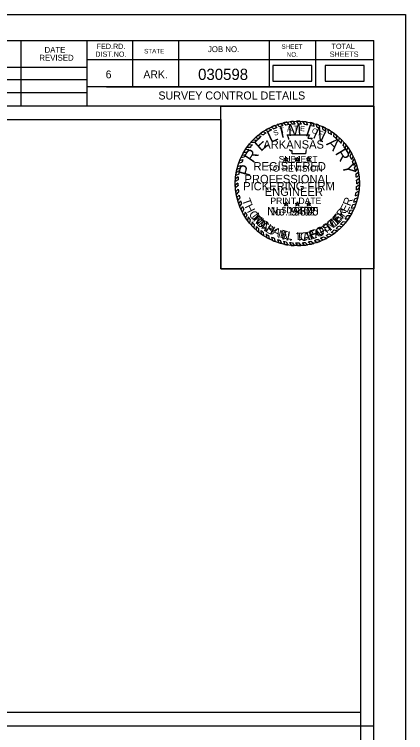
# Model space of a CAD drawing. Extents: x 818639 to 819473, y 1805980 to 1806194.
# Drawn here: x 818913.8 to 818972.5, y 1806086 to 1806193.7 of the extents above; entities that cross this region are included whole.
import ezdxf

# ---------------------------------------------------------------- set-up
doc = ezdxf.new("R2010")
doc.units = 0
for name, color, linetype in [('R_Border', 7, 'Continuous'), ('R_Border Notes', 7, 'Continuous'), ('R_Border Plan-Plan', 7, 'Continuous'), ('R_Border Title', 7, 'Continuous'), ('R_No Plot', 7, 'Continuous'), ('STAMP_PE_CRAFTON', 7, 'Continuous'), ('STAMP_PE_FOSTER', 7, 'Continuous'), ('STAMP_PE_SEAL-INFO', 7, 'Continuous'), ('STAMP_PE_TAEGTMEYER', 7, 'Continuous'), ('STAMP_PE_TXT', 7, 'Continuous'), ('STAMP_PRELIMINARY', 7, 'Continuous')]:
    doc.layers.add(name, color=color, linetype=linetype)

msp = doc.modelspace()

# ---------------------------------------------------------------- linework, layer by layer
at = {"layer": 'R_Border'}
for p, q in [((818651.6, 1806189.77), (818967.78, 1806189.77)), ((818914.82, 1806179.89), (818914.82, 1806189.77)), ((818924.68, 1806189.77), (818924.68, 1806179.89)), ((818931.52, 1806189.77), (818931.52, 1806182.83)), ((818938.46, 1806189.77), (818938.46, 1806182.83)), ((818952.04, 1806189.77), (818952.04, 1806182.83)), ((818958.98, 1806189.77), (818958.98, 1806182.83)), ((818967.78, 1805984.31), (818967.78, 1806189.77)), ((818967.78, 1806186.83), (818924.68, 1806186.83)), ((818967.78, 1806186.85), (818967.78, 1806186.85)), ((818905.14, 1806185.75), (818924.68, 1806185.75)), ((818905.14, 1806183.89), (818924.68, 1806183.89)), ((818905.14, 1806181.95), (818924.68, 1806181.95)), ((818967.78, 1806182.83), (818924.68, 1806182.83)), ((818927.64, 1806182.83), (818967.78, 1806182.83)), ((818967.78, 1806179.89), (818905.14, 1806179.89))]:
    msp.add_line(p, q, dxfattribs=at)
at = {"layer": 'R_Border Plan-Plan'}
msp.add_line((818651.6, 1806087.04), (818967.78, 1806087.04), dxfattribs=at)
at = {"layer": 'R_Border Title'}
for points in [[(818952.59, 1806183.68), (818958.43, 1806183.68), (818958.43, 1806185.99), (818952.59, 1806185.99)], [(818960.46, 1806183.68), (818966.3, 1806183.68), (818966.3, 1806185.99), (818960.46, 1806185.99)]]:
    msp.add_lwpolyline(points, close=True, dxfattribs=at)
at = {"layer": 'R_No Plot'}
for points in [[(818639.19, 1806193.67), (818972.53, 1806193.67), (818972.53, 1805980.33), (818639.19, 1805980.33)], [(818965.78, 1806089.04), (818653.6, 1806089.04), (818653.6, 1806187.77), (818903.14, 1806187.77), (818903.14, 1806177.89), (818920.68, 1806177.89), (818944.78, 1806177.89), (818944.78, 1806155.56), (818965.78, 1806155.56)], [(818653.6, 1806187.77), (818903.14, 1806187.77), (818903.14, 1806177.89), (818920.68, 1806177.89), (818944.78, 1806177.89), (818944.78, 1806155.56), (818965.78, 1806155.56), (818965.78, 1805986.31), (818653.6, 1805986.31)], [(818944.78, 1806179.89), (818967.78, 1806179.89), (818967.78, 1806155.56), (818944.78, 1806155.56)]]:
    msp.add_lwpolyline(points, close=True, dxfattribs=at)
at = {"layer": 'STAMP_PE_SEAL-INFO'}
for p, q in [((818954.7, 1806177.52), (818955, 1806177.16)), ((818955.22, 1806177.6), (818955.5, 1806177.21)), ((818955.95, 1806177.24), (818955.64, 1806177.64)), ((818956.45, 1806177.25), (818956.17, 1806177.66)), ((818956.91, 1806177.23), (818956.65, 1806177.65)), ((818957.41, 1806177.18), (818957.12, 1806177.62)), ((818957.84, 1806177.11), (818957.58, 1806177.57)), ((818951.95, 1806176.59), (818952.42, 1806176.37)), ((818952.38, 1806176.8), (818952.77, 1806176.53)), ((818952.89, 1806177.02), (818953.19, 1806176.69)), ((818953.24, 1806177.15), (818953.62, 1806176.84)), ((818953.83, 1806177.33), (818954.12, 1806176.98)), ((818954.22, 1806177.43), (818954.58, 1806177.08)), ((818958.4, 1806176.99), (818958.23, 1806177.45)), ((818958.8, 1806176.88), (818958.64, 1806177.35)), ((818959.26, 1806176.74), (818959.11, 1806177.22)), ((818959.67, 1806176.58), (818959.53, 1806177.07)), ((818960.14, 1806176.37), (818960.03, 1806176.87)), ((818960.58, 1806176.14), (818960.49, 1806176.65)), ((818960.97, 1806175.92), (818960.93, 1806176.42)), ((818950.32, 1806175.5), (818950.85, 1806175.4)), ((818950.7, 1806175.83), (818951.15, 1806175.63)), ((818951.12, 1806176.1), (818951.56, 1806175.9)), ((818951.51, 1806176.34), (818951.94, 1806176.12)), ((818954.75, 1806175.63), (818958.1, 1806175.63)), ((818954.88, 1806175.32), (818954.75, 1806175.63)), ((818958.1, 1806175.63), (818957.87, 1806175.13)), ((818961.4, 1806175.63), (818961.37, 1806176.14)), ((818961.76, 1806175.36), (818961.8, 1806175.85)), ((818962.21, 1806174.99), (818962.23, 1806175.51)), ((818949.32, 1806174.54), (818949.84, 1806174.5)), ((818949.64, 1806174.88), (818950.19, 1806174.84)), ((818949.98, 1806175.2), (818950.44, 1806175.07)), ((818954.98, 1806175.02), (818954.88, 1806175.32)), ((818954.99, 1806174.91), (818954.98, 1806175.02)), ((818957.87, 1806175.13), (818958.51, 1806175.13)), ((818958.51, 1806175.13), (818958.36, 1806174.91)), ((818962.52, 1806174.7), (818962.59, 1806175.2)), ((818962.88, 1806174.32), (818962.95, 1806174.85)), ((818963.16, 1806174.01), (818963.29, 1806174.48)), ((818948.46, 1806173.41), (818948.98, 1806173.45)), ((818948.7, 1806173.76), (818949.2, 1806173.75)), ((818948.97, 1806174.13), (818949.52, 1806174.15)), ((818955.18, 1806173.2), (818955.15, 1806173.42)), ((818955.49, 1806173.2), (818955.18, 1806173.2)), ((818955.49, 1806172.77), (818955.49, 1806173.2)), ((818957.62, 1806173.42), (818957.54, 1806173.11)), ((818963.48, 1806173.59), (818963.61, 1806174.09)), ((818963.7, 1806173.28), (818963.88, 1806173.74)), ((818964.01, 1806172.78), (818964.19, 1806173.27)), ((818947.8, 1806172.2), (818948.3, 1806172.3)), ((818947.98, 1806172.59), (818948.48, 1806172.65)), ((818948.22, 1806173.01), (818948.7, 1806173.03)), ((818957.52, 1806172.77), (818955.49, 1806172.77)), ((818957.54, 1806173.11), (818957.52, 1806172.77)), ((818964.21, 1806172.41), (818964.43, 1806172.86)), ((818964.44, 1806171.93), (818964.66, 1806172.41)), ((818947.31, 1806170.86), (818947.78, 1806171.03)), ((818947.46, 1806171.36), (818947.95, 1806171.5)), ((818947.61, 1806171.77), (818948.12, 1806171.91)), ((818964.58, 1806171.59), (818964.84, 1806172.02)), ((818964.77, 1806171.04), (818965.04, 1806171.52)), ((818964.88, 1806170.68), (818965.17, 1806171.13)), ((818947.57, 1806170.2), (818947.1, 1806169.95)), ((818947.2, 1806170.45), (818947.67, 1806170.64)), ((818965.01, 1806170.12), (818965.33, 1806170.57)), ((818965.08, 1806169.74), (818965.44, 1806170.09)), ((818947.38, 1806168.88), (818946.96, 1806168.63)), ((818947.42, 1806169.31), (818946.98, 1806169.03)), ((818947.48, 1806169.74), (818947.03, 1806169.52)), ((818965.15, 1806169.23), (818965.52, 1806169.57)), ((818965.18, 1806168.81), (818965.57, 1806169.1)), ((818947.37, 1806168.39), (818946.96, 1806168.05)), ((818947.37, 1806167.98), (818946.98, 1806167.66)), ((818965.18, 1806167.89), (818965.6, 1806168.17)), ((818965.19, 1806168.29), (818965.6, 1806168.62)), ((818947.41, 1806167.49), (818947.04, 1806167.13)), ((818947.46, 1806167.06), (818947.11, 1806166.69)), ((818965.09, 1806166.99), (818965.54, 1806167.21)), ((818965.14, 1806167.38), (818965.58, 1806167.64)), ((818947.54, 1806166.6), (818947.2, 1806166.23)), ((818947.63, 1806166.18), (818947.32, 1806165.77)), ((818947.76, 1806165.73), (818947.46, 1806165.32)), ((818964.75, 1806165.55), (818965.24, 1806165.75)), ((818964.89, 1806166.04), (818965.37, 1806166.24)), ((818965, 1806166.49), (818965.46, 1806166.69)), ((818947.9, 1806165.31), (818947.61, 1806164.9)), ((818948.06, 1806164.88), (818947.8, 1806164.46)), ((818964.4, 1806164.65), (818964.89, 1806164.75)), ((818964.61, 1806165.17), (818965.1, 1806165.3)), ((818948.23, 1806164.5), (818948.01, 1806164.04)), ((818948.47, 1806164.04), (818948.28, 1806163.55)), ((818948.7, 1806163.64), (818948.52, 1806163.17)), ((818963.79, 1806163.54), (818964.27, 1806163.53)), ((818963.97, 1806163.82), (818964.47, 1806163.87)), ((818964.24, 1806164.32), (818964.73, 1806164.39)), ((818948.91, 1806163.33), (818948.8, 1806162.78)), ((818949.19, 1806162.94), (818949.09, 1806162.41)), ((818949.49, 1806162.56), (818949.41, 1806162.04)), ((818963.15, 1806162.65), (818963.61, 1806162.57)), ((818963.45, 1806163.04), (818963.96, 1806163.05)), ((818949.79, 1806162.22), (818949.73, 1806161.7)), ((818950.12, 1806161.9), (818950.09, 1806161.37)), ((818950.46, 1806161.58), (818950.46, 1806161.05)), ((818961.83, 1806161.36), (818962.3, 1806161.22)), ((818962.1, 1806161.58), (818962.57, 1806161.46)), ((818962.51, 1806161.96), (818962.95, 1806161.82)), ((818962.76, 1806162.22), (818963.24, 1806162.13)), ((818950.82, 1806161.29), (818950.84, 1806160.76)), ((818951.16, 1806161.04), (818951.2, 1806160.52)), ((818951.59, 1806160.76), (818951.65, 1806160.25)), ((818951.94, 1806160.55), (818952.03, 1806160.04)), ((818952.42, 1806160.3), (818952.57, 1806159.78)), ((818960.2, 1806160.33), (818960.69, 1806160.12)), ((818960.61, 1806160.54), (818961.03, 1806160.31)), ((818961.03, 1806160.79), (818961.48, 1806160.59)), ((818961.37, 1806161.02), (818961.81, 1806160.83)), ((818952.79, 1806160.13), (818952.96, 1806159.62)), ((818953.28, 1806159.94), (818953.49, 1806159.44)), ((818953.69, 1806159.81), (818953.92, 1806159.32)), ((818954.2, 1806159.67), (818954.41, 1806159.2)), ((818954.6, 1806159.58), (818954.85, 1806159.12)), ((818955.1, 1806159.5), (818955.34, 1806159.06)), ((818955.54, 1806159.45), (818955.81, 1806159.02)), ((818956.02, 1806159.43), (818956.32, 1806159.01)), ((818956.48, 1806159.42), (818956.82, 1806159.03)), ((818957, 1806159.45), (818957.32, 1806159.07)), ((818957.44, 1806159.5), (818957.81, 1806159.14)), ((818957.88, 1806159.57), (818958.27, 1806159.23)), ((818958.37, 1806159.67), (818958.75, 1806159.35)), ((818958.83, 1806159.79), (818959.25, 1806159.5)), ((818959.33, 1806159.96), (818959.77, 1806159.69)), ((818959.75, 1806160.12), (818960.17, 1806159.86))]:
    msp.add_line(p, q, dxfattribs=at)
for radius, start, end in [(9.32, 99.7525, 102.7765), (9.32, 93.9381, 96.5517), (9.32, 87.7298, 90.6707), (9.32, 81.9732, 84.8236), (9.32, 117.6544, 120.8099), (9.32, 111.3124, 114.7026), (8.91, 110.3086, 113.1659), (9.32, 105.2339, 109.0352), (8.91, 104.0352, 107.3615), (8.91, 98.258, 101.0329), (8.91, 92.1102, 95.0367), (8.91, 85.9628, 88.9097), (8.91, 79.9264, 82.696), (9.32, 75.3125, 77.9426), (8.91, 73.5575, 76.2314), (9.32, 69.6061, 72.3058), (8.91, 67.6248, 70.504), (9.32, 63.1329, 66.2704), (9.32, 56.9003, 60.0942), (9.32, 129.7326, 132.5376), (8.91, 127.5297, 130.9683), (9.32, 123.6199, 126.5906), (8.91, 121.9746, 125.11), (8.91, 115.6869, 119.1583), (8.91, 61.1558, 64.3784), (8.91, 54.9238, 58.2702), (8.91, 48.3016, 52.0395), (9.32, 50.3492, 53.7159), (9.32, 135.4021, 138.3031), (8.91, 133.1331, 136.2562), (8.91, 42.2212, 45.5512), (9.32, 44.3405, 47.3929), (9.32, 38.1247, 41.2316), (9.32, 147.0072, 149.899), (9.32, 141.6056, 144.4486), (8.91, 145.0197, 148.2104), (8.91, 139.301, 142.5873), (8.91, 36.135, 39.5311), (8.91, 29.9032, 33.6645), (9.32, 31.9614, 35.4294), (9.32, 152.864, 155.5189), (8.91, 151.0315, 153.573), (8.91, 23.7732, 27.2211), (9.32, 25.9391, 29.0125), (9.32, 158.4077, 161.0701), (8.91, 162.4331, 165.0013), (8.91, 156.3402, 159.2319), (8.91, 17.6802, 21.4251), (9.32, 19.9538, 23.3141), (9.32, 13.8421, 17.4447), (9.32, 170.0003, 172.6878), (9.32, 164.3068, 166.894), (8.91, 167.9048, 170.9039), (8.91, 11.5444, 15.2364), (9.32, 7.5852, 10.8621), (9.32, 175.7409, 178.2066), (8.91, 173.73, 176.4734), (8.91, 5.7599, 9.0606), (9.32, 1.7215, 4.7268), (9.32, 181.7251, 184.1626), (8.91, 179.6454, 182.2633), (8.91, 353.8632, 357.1274), (8.91, 359.7329, 3.0639), (9.32, 355.7156, 358.9569), (9.32, 187.4204, 190.1927), (8.91, 185.4539, 188.234), (8.91, 348.0778, 351.3435), (9.32, 349.8305, 353.0885), (9.32, 193.0369, 195.9973), (8.91, 191.2274, 193.9858), (8.91, 196.9675, 199.8353), (8.91, 341.777, 345.0925), (9.32, 343.8925, 347.035), (9.32, 198.8967, 201.6281), (8.91, 202.7761, 205.4791), (8.91, 335.6038, 339.1858), (9.32, 337.3837, 340.9933), (9.32, 204.5479, 207.4328), (9.32, 210.8636, 213.6571), (8.91, 208.7883, 211.7934), (8.91, 323.5851, 327.4407), (9.32, 325.4405, 328.9872), (8.91, 329.5549, 333.2076), (9.32, 331.4037, 334.9332), (9.32, 216.6115, 219.491), (8.91, 214.1838, 217.2747), (8.91, 220.3909, 223.3056), (8.91, 316.6531, 320.3711), (9.32, 318.2846, 321.8043), (9.32, 222.48, 225.3801), (9.32, 228.3665, 231.348), (8.91, 226.2494, 229.2407), (8.91, 304.823, 308.5143), (8.91, 310.7744, 314.3161), (9.32, 312.4518, 315.6633), (8.91, 232.229, 234.9336), (9.32, 234.295, 236.9452), (8.91, 238.2223, 240.8353), (8.91, 244.3204, 246.9486), (8.91, 292.8745, 296.1185), (8.91, 299.0768, 302.1724), (9.32, 300.621, 303.8703), (9.32, 306.3721, 310.208), (9.32, 240.1977, 242.8613), (9.32, 246.576, 249.1558), (8.91, 250.3491, 253.1216), (9.32, 252.5967, 255.3252), (8.91, 256.505, 259.1192), (9.32, 258.4433, 261.1398), (8.91, 262.3783, 265.2012), (8.91, 268.3215, 271.277), (8.91, 274.6157, 277.4486), (8.91, 280.3459, 283.5814), (9.32, 282.3199, 285.3702), (8.91, 286.6423, 289.9783), (9.32, 288.5709, 291.9733), (9.32, 294.6481, 298.2166), (9.32, 264.1978, 267.1009), (9.32, 270.2548, 273.3361), (9.32, 276.4239, 279.4357)]:
    msp.add_arc((818956.28, 1806168.33), radius, start, end, dxfattribs=at)
at = {"layer": 'STAMP_PE_TXT'}
for p, q in [((818954.51, 1806172.05), (818954.58, 1806172.28)), ((818954.58, 1806172.28), (818954.66, 1806172.05)), ((818956.21, 1806172.05), (818956.28, 1806172.28)), ((818956.28, 1806172.28), (818956.36, 1806172.05)), ((818957.9, 1806172.05), (818957.98, 1806172.28)), ((818957.98, 1806172.28), (818958.05, 1806172.05)), ((818954.46, 1806171.91), (818954.26, 1806172.05)), ((818954.26, 1806172.05), (818954.51, 1806172.05)), ((818954.38, 1806171.67), (818954.46, 1806171.91)), ((818954.58, 1806171.82), (818954.38, 1806171.67)), ((818954.78, 1806171.67), (818954.58, 1806171.82)), ((818954.66, 1806172.05), (818954.9, 1806172.05)), ((818954.9, 1806172.05), (818954.71, 1806171.91)), ((818954.71, 1806171.91), (818954.78, 1806171.67)), ((818956.16, 1806171.91), (818955.96, 1806172.05)), ((818955.96, 1806172.05), (818956.21, 1806172.05)), ((818956.08, 1806171.67), (818956.16, 1806171.91)), ((818956.28, 1806171.82), (818956.08, 1806171.67)), ((818956.48, 1806171.67), (818956.28, 1806171.82)), ((818956.36, 1806172.05), (818956.6, 1806172.05)), ((818956.6, 1806172.05), (818956.4, 1806171.91)), ((818956.4, 1806171.91), (818956.48, 1806171.67)), ((818957.86, 1806171.91), (818957.66, 1806172.05)), ((818957.66, 1806172.05), (818957.9, 1806172.05)), ((818957.78, 1806171.67), (818957.86, 1806171.91)), ((818957.98, 1806171.82), (818957.78, 1806171.67)), ((818958.18, 1806171.67), (818957.98, 1806171.82)), ((818958.05, 1806172.05), (818958.3, 1806172.05)), ((818958.3, 1806172.05), (818958.1, 1806171.91)), ((818958.1, 1806171.91), (818958.18, 1806171.67)), ((818954.46, 1806165.2), (818954.26, 1806165.34)), ((818954.26, 1806165.34), (818954.51, 1806165.34)), ((818954.38, 1806164.97), (818954.46, 1806165.2)), ((818954.58, 1806165.11), (818954.38, 1806164.97)), ((818954.51, 1806165.34), (818954.58, 1806165.58)), ((818954.58, 1806165.58), (818954.66, 1806165.34)), ((818954.78, 1806164.97), (818954.58, 1806165.11)), ((818954.66, 1806165.34), (818954.9, 1806165.34)), ((818954.9, 1806165.34), (818954.71, 1806165.2)), ((818954.71, 1806165.2), (818954.78, 1806164.97)), ((818956.16, 1806165.2), (818955.96, 1806165.34)), ((818955.96, 1806165.34), (818956.21, 1806165.34)), ((818956.08, 1806164.97), (818956.16, 1806165.2)), ((818956.28, 1806165.11), (818956.08, 1806164.97)), ((818956.21, 1806165.34), (818956.28, 1806165.58)), ((818956.28, 1806165.58), (818956.36, 1806165.34)), ((818956.48, 1806164.97), (818956.28, 1806165.11)), ((818956.36, 1806165.34), (818956.6, 1806165.34)), ((818956.6, 1806165.34), (818956.4, 1806165.2)), ((818956.4, 1806165.2), (818956.48, 1806164.97)), ((818957.86, 1806165.2), (818957.66, 1806165.34)), ((818957.66, 1806165.34), (818957.9, 1806165.34)), ((818957.78, 1806164.97), (818957.86, 1806165.2)), ((818957.98, 1806165.11), (818957.78, 1806164.97)), ((818957.9, 1806165.34), (818957.98, 1806165.58)), ((818957.98, 1806165.58), (818958.05, 1806165.34)), ((818958.18, 1806164.97), (818957.98, 1806165.11)), ((818958.05, 1806165.34), (818958.3, 1806165.34)), ((818958.3, 1806165.34), (818958.1, 1806165.2)), ((818958.1, 1806165.2), (818958.18, 1806164.97))]:
    msp.add_line(p, q, dxfattribs=at)
at = {"layer": 'STAMP_PRELIMINARY'}
msp.add_circle((818956.28, 1806168.33), 9.32, dxfattribs=at)

# ---------------------------------------------------------------- texts
at = {"layer": 'R_Border'}
for s, height, p in [('DATE', 0.879, (818918.34, 1806187.91)), ('FED.RD.', 0.782, (818926.16, 1806188.49)), ('STATE', 0.684, (818933.28, 1806187.81)), ('JOB NO.', 0.879, (818942.86, 1806188.01)), ('SHEET', 0.684, (818953.9, 1806188.49)), ('TOTAL', 0.782, (818961.42, 1806188.49)), ('REVISED', 0.879, (818917.56, 1806186.73)), ('DIST.NO.', 0.782, (818925.96, 1806187.31)), ('NO.', 0.684, (818954.68, 1806187.31)), ('SHEETS', 0.782, (818961.14, 1806187.31)), ('6', 1.17, (818927.52, 1806184.09)), ('ARK.', 1.172, (818933.18, 1806184.09))]:
    msp.add_text(s, height=height, dxfattribs=at).set_placement(p)
at = {"layer": 'R_Border Notes'}
for s, height, p in [('030598', 1.68, (818941.39, 1806183.84)), ('SURVEY CONTROL DETAILS', 1.2, (818935.43, 1806180.91))]:
    msp.add_text(s, height=height, dxfattribs=at).set_placement(p)
at = {"layer": 'STAMP_PE_CRAFTON'}
msp.add_text('No. 12370', height=1.25, dxfattribs=at).set_placement((818951.74, 1806163.53))
for s, rotation, p in [('T', 310.7442, (818949.25, 1806163.23)), ('N', 49.2411, (818962.56, 1806162.36)), ('O', 317.6422, (818949.91, 1806162.42)), ('N', 324.4537, (818950.76, 1806161.64)), ('T', 34.1136, (818960.86, 1806160.97)), ('O', 41.8391, (818961.72, 1806161.58)), ('Y', 331.1686, (818951.79, 1806160.92)), ('A', 20.5125, (818958.96, 1806160.09)), ('F', 28.7821, (818959.94, 1806160.46)), ('N', 347.4752, (818953.85, 1806160)), ('C', 6.0117, (818956.75, 1806159.68)), ('R', 14.8189, (818957.85, 1806159.79)), ('.', 356.8926, (818955.08, 1806159.73))]:
    msp.add_text(s, height=1.25, rotation=rotation, dxfattribs=at).set_placement(p)
at = {"layer": 'STAMP_PE_FOSTER'}
msp.add_text('No. 9402', height=1.25, dxfattribs=at).set_placement((818952.27, 1806163.53))
for s, rotation, p in [('R', 54.5031, (818963.01, 1806163.15)), ('M', 308.339, (818949.4, 1806163.36)), ('E', 46.9613, (818962.28, 1806162.33)), ('I', 314.1842, (818950.19, 1806162.42)), ('C', 319.8733, (818950.55, 1806162.07)), ('T', 39.4194, (818961.42, 1806161.58)), ('H', 327.7235, (818951.48, 1806161.33)), ('A', 335.7276, (818952.46, 1806160.75)), ('E', 343.5779, (818953.6, 1806160.28)), ('F', 15.8691, (818958.32, 1806160.09)), ('O', 23.719, (818959.36, 1806160.42)), ('S', 31.7234, (818960.47, 1806160.95)), ('L', 350.8115, (818954.65, 1806160)), ('L', 1.2666, (818956.19, 1806159.84)), ('.', 6.8035, (818957.24, 1806159.9))]:
    msp.add_text(s, height=1.2, rotation=rotation, dxfattribs=at).set_placement(p)
at = {"layer": 'STAMP_PE_TAEGTMEYER'}
for s, rotation, p in [('T', 289.646, (818947.98, 1806165.85)), ('R', 69.57, (818964.23, 1806164.85)), ('H', 296.7339, (818948.34, 1806164.86)), ('E', 63.0984, (818963.73, 1806163.87)), ('O', 303.7708, (818948.93, 1806163.75)), ('M', 314.2033, (818949.58, 1806162.8)), ('E', 46.8094, (818962.32, 1806162.11)), ('Y', 53.9986, (818963.06, 1806162.93)), ('A', 321.0594, (818950.54, 1806161.84)), ('M', 39.3, (818961.28, 1806161.23)), ('S', 327.8239, (818951.37, 1806161.19)), ('N', 344.2727, (818953.27, 1806160.19)), ('E', 17.6836, (818958.23, 1806159.87)), ('G', 23.3052, (818959.28, 1806160.2)), ('T', 31.466, (818960.38, 1806160.69)), ('T', 3.0061, (818956.15, 1806159.66)), ('A', 8.9826, (818957.19, 1806159.71)), ('.', 350.6464, (818954.48, 1806159.85))]:
    msp.add_text(s, height=1.25, rotation=rotation, dxfattribs=at).set_placement(p)
msp.add_text('No. 19605', height=1.25, dxfattribs=at).set_placement((818951.74, 1806163.53))
at = {"layer": 'STAMP_PE_TXT'}
for s, rotation, p in [('T', 16.311, (818953.8, 1806175.81)), ('A', 9.0679, (818954.76, 1806176.06)), ('T', 1.8248, (818955.75, 1806176.19)), ('E', 355.2002, (818956.66, 1806176.2)), ('O', 342.2506, (818958.39, 1806175.93)), ('S', 23.5541, (818952.88, 1806175.44)), ('F', 335.0075, (818959.35, 1806175.59))]:
    msp.add_text(s, height=0.781, rotation=rotation, dxfattribs=at).set_placement(p)
for s, p in [('ARKANSAS', (818951.17, 1806173.55)), ('REGISTERED', (818949.7, 1806170.28)), ('PROFESSIONAL', (818948.35, 1806168.37)), ('ENGINEER', (818951.39, 1806166.47))]:
    msp.add_text(s, height=1.25, dxfattribs=at).set_placement(p)
at = {"layer": 'STAMP_PRELIMINARY'}
for s, rotation, p in [('I', 12.5248, (818953.82, 1806175.12)), ('M', 3.1074, (818954.92, 1806175.43)), ('I', 342.3164, (818957.38, 1806175.5)), ('N', 333.9382, (818958.49, 1806175.22)), ('E', 42.3578, (818950.81, 1806173.03)), ('L', 25.513, (818952.29, 1806174.36)), ('A', 315.6579, (818960.53, 1806174.2)), ('R', 56.2292, (818949.65, 1806171.3)), ('R', 301.3831, (818961.89, 1806172.88)), ('P', 73.913, (818949.1, 1806169.28)), ('Y', 283.2593, (818962.98, 1806171.1))]:
    msp.add_text(s, height=1.8, rotation=rotation, dxfattribs=at).set_placement(p)
for s, height, p in [('SUBJECT', 0.96, (818953.48, 1806171.48)), ('TO REVISION', 0.96, (818951.82, 1806170.1)), ('PICKERING FIRM', 1.25, (818948.15, 1806167.3)), ('PRINT DATE', 0.96, (818952.24, 1806165.25)), ('$DATE$', 0.96, (818953.92, 1806163.87))]:
    msp.add_text(s, height=height, dxfattribs=at).set_placement(p)

doc.saveas('drawing.dxf')
